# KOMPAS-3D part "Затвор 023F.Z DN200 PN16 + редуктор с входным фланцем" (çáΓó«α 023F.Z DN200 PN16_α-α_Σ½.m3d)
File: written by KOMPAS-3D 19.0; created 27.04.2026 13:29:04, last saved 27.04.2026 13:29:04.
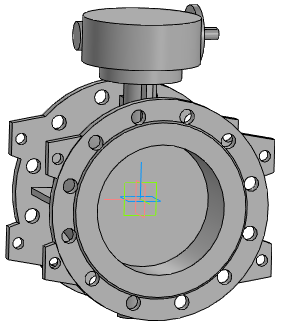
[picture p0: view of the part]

Document properties: Полное имя файла: ..\..\Затвор 023F.Z DN200-DN1600_редуктор с входным фланцем\Затвор 023F.Z DN200 PN16 + редуктор с входным фланцем.a3d

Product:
- Part/product: Затвор 023F.Z DN200 PN16 + редуктор с входным фланцем
    Масса: 59.2421

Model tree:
1. Операция без истории:1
